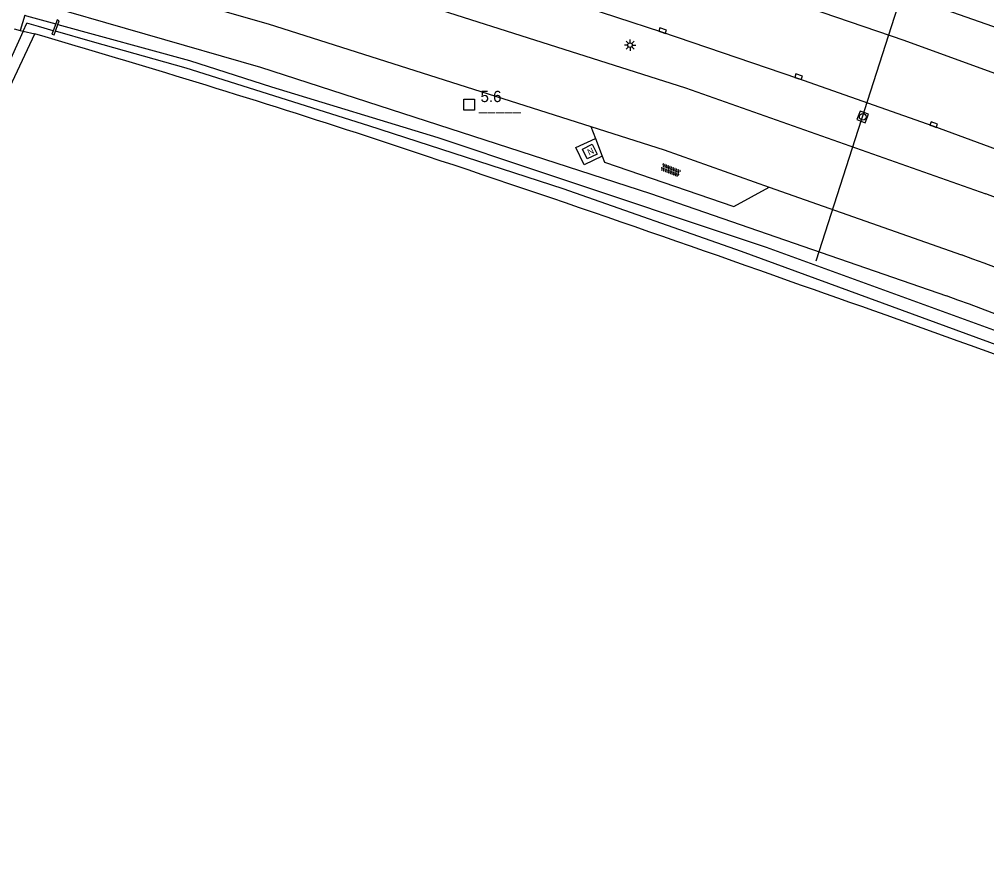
# Model space of a CAD drawing. Extents: x 133000 to 136000, y 400500 to 403500.
# Drawn here: x 134471.1 to 134578.4, y 401013 to 401106.1 of the extents above; entities that cross this region are included whole.
import ezdxf

# ---------------------------------------------------------------- set-up
doc = ezdxf.new("R2010")
doc.units = 0
for name, color, linetype in [('gg-knt-verharding', 7, 'Continuous'), ('gg-kntw-bovenkant insteek waterloop', 7, 'Continuous'), ('gg-kntw-waterlijn', 7, 'Continuous'), ('gg-kwrk-duiker nz buis', 7, 'Continuous'), ('gg-kwrk-kunstwerk', 7, 'Continuous'), ('gt-anno-nummer hm paal', 7, 'Continuous'), ('gt-grn-vlakafsluiter', 7, 'Continuous'), ('gt-symb-hm paal', 7, 'Continuous'), ('gt-symb-kolk', 7, 'Continuous'), ('gt-symb-lichtmast', 7, 'Continuous'), ('gt-symb-nortonput', 7, 'Continuous'), ('gt-symb-overige verharding', 7, 'Continuous'), ('gt-symb-rioolschacht', 7, 'Continuous')]:
    doc.layers.add(name, color=color, linetype=linetype)

# ---------------------------------------------------------------- blocks, each defined once
blk = doc.blocks.new('gt0-OVH')
at = {"layer": 'gt-symb-overige verharding'}
for points in [[(-0.97, 0.3), (-0.97, 0.31), (-0.96, 0.32), (-0.97, 0.33), (-0.97, 0.34), (-0.98, 0.35), (-0.99, 0.35), (-1, 0.36), (-1.01, 0.35), (-1.02, 0.35), (-1.03, 0.34), (-1.03, 0.33), (-1.04, 0.32), (-1.03, 0.31), (-1.03, 0.3), (-1.02, 0.29), (-1.01, 0.29), (-1, 0.28), (-0.99, 0.29), (-0.98, 0.29)], [(-0.87, 0.11), (-0.87, 0.12), (-0.86, 0.13), (-0.87, 0.14), (-0.87, 0.15), (-0.88, 0.16), (-0.89, 0.16), (-0.9, 0.16), (-0.91, 0.16), (-0.92, 0.16), (-0.93, 0.15), (-0.93, 0.14), (-0.94, 0.13), (-0.93, 0.12), (-0.93, 0.11), (-0.92, 0.1), (-0.91, 0.09), (-0.9, 0.09), (-0.89, 0.09), (-0.88, 0.1)], [(-0.77, 0.3), (-0.77, 0.31), (-0.76, 0.32), (-0.77, 0.33), (-0.77, 0.34), (-0.78, 0.35), (-0.79, 0.35), (-0.8, 0.36), (-0.81, 0.35), (-0.82, 0.35), (-0.83, 0.34), (-0.83, 0.33), (-0.84, 0.32), (-0.83, 0.31), (-0.83, 0.3), (-0.82, 0.29), (-0.81, 0.29), (-0.8, 0.28), (-0.79, 0.29), (-0.78, 0.29)], [(-0.67, 0.11), (-0.67, 0.12), (-0.66, 0.13), (-0.67, 0.14), (-0.67, 0.15), (-0.68, 0.16), (-0.69, 0.16), (-0.7, 0.16), (-0.71, 0.16), (-0.72, 0.16), (-0.73, 0.15), (-0.73, 0.14), (-0.74, 0.13), (-0.73, 0.12), (-0.73, 0.11), (-0.72, 0.1), (-0.71, 0.09), (-0.7, 0.09), (-0.69, 0.09), (-0.68, 0.1)], [(-0.57, 0.3), (-0.57, 0.31), (-0.56, 0.32), (-0.57, 0.33), (-0.57, 0.34), (-0.58, 0.35), (-0.59, 0.35), (-0.6, 0.36), (-0.61, 0.35), (-0.62, 0.35), (-0.63, 0.34), (-0.63, 0.33), (-0.64, 0.32), (-0.63, 0.31), (-0.63, 0.3), (-0.62, 0.29), (-0.61, 0.29), (-0.6, 0.28), (-0.59, 0.29), (-0.58, 0.29)], [(-0.47, 0.11), (-0.47, 0.12), (-0.46, 0.13), (-0.47, 0.14), (-0.47, 0.15), (-0.48, 0.16), (-0.49, 0.16), (-0.5, 0.16), (-0.51, 0.16), (-0.52, 0.16), (-0.53, 0.15), (-0.53, 0.14), (-0.54, 0.13), (-0.53, 0.12), (-0.53, 0.11), (-0.52, 0.1), (-0.51, 0.09), (-0.5, 0.09), (-0.49, 0.09), (-0.48, 0.1)], [(-0.37, 0.3), (-0.37, 0.31), (-0.36, 0.32), (-0.37, 0.33), (-0.37, 0.34), (-0.38, 0.35), (-0.39, 0.35), (-0.4, 0.36), (-0.41, 0.35), (-0.42, 0.35), (-0.43, 0.34), (-0.43, 0.33), (-0.44, 0.32), (-0.43, 0.31), (-0.43, 0.3), (-0.42, 0.29), (-0.41, 0.29), (-0.4, 0.28), (-0.39, 0.29), (-0.38, 0.29)], [(-0.27, 0.11), (-0.27, 0.12), (-0.26, 0.13), (-0.27, 0.14), (-0.27, 0.15), (-0.28, 0.16), (-0.29, 0.16), (-0.3, 0.16), (-0.31, 0.16), (-0.32, 0.16), (-0.33, 0.15), (-0.33, 0.14), (-0.34, 0.13), (-0.33, 0.12), (-0.33, 0.11), (-0.32, 0.1), (-0.31, 0.09), (-0.3, 0.09), (-0.29, 0.09), (-0.28, 0.1)], [(-0.17, 0.3), (-0.17, 0.31), (-0.16, 0.32), (-0.17, 0.33), (-0.17, 0.34), (-0.18, 0.35), (-0.19, 0.35), (-0.2, 0.36), (-0.21, 0.35), (-0.22, 0.35), (-0.23, 0.34), (-0.23, 0.33), (-0.24, 0.32), (-0.23, 0.31), (-0.23, 0.3), (-0.22, 0.29), (-0.21, 0.29), (-0.2, 0.28), (-0.19, 0.29), (-0.18, 0.29)], [(-0.07, 0.11), (-0.07, 0.12), (-0.06, 0.13), (-0.07, 0.14), (-0.07, 0.15), (-0.08, 0.16), (-0.09, 0.16), (-0.1, 0.16), (-0.11, 0.16), (-0.12, 0.16), (-0.13, 0.15), (-0.13, 0.14), (-0.14, 0.13), (-0.13, 0.12), (-0.13, 0.11), (-0.12, 0.1), (-0.11, 0.09), (-0.1, 0.09), (-0.09, 0.09), (-0.08, 0.1)], [(0.03, 0.3), (0.03, 0.31), (0.04, 0.32), (0.03, 0.33), (0.03, 0.34), (0.02, 0.35), (0.01, 0.35), (0, 0.36), (-0.01, 0.35), (-0.02, 0.35), (-0.03, 0.34), (-0.03, 0.33), (-0.04, 0.32), (-0.03, 0.31), (-0.03, 0.3), (-0.02, 0.29), (-0.01, 0.29), (0, 0.28), (0.01, 0.29), (0.02, 0.29)], [(0.13, 0.11), (0.13, 0.12), (0.14, 0.13), (0.13, 0.14), (0.13, 0.15), (0.12, 0.16), (0.11, 0.16), (0.1, 0.16), (0.09, 0.16), (0.08, 0.16), (0.07, 0.15), (0.07, 0.14), (0.06, 0.13), (0.07, 0.12), (0.07, 0.11), (0.08, 0.1), (0.09, 0.09), (0.1, 0.09), (0.11, 0.09), (0.12, 0.1)], [(0.23, 0.3), (0.23, 0.31), (0.24, 0.32), (0.23, 0.33), (0.23, 0.34), (0.22, 0.35), (0.21, 0.35), (0.2, 0.36), (0.19, 0.35), (0.18, 0.35), (0.17, 0.34), (0.17, 0.33), (0.16, 0.32), (0.17, 0.31), (0.17, 0.3), (0.18, 0.29), (0.19, 0.29), (0.2, 0.28), (0.21, 0.29), (0.22, 0.29)], [(0.33, 0.11), (0.33, 0.12), (0.34, 0.13), (0.33, 0.14), (0.33, 0.15), (0.32, 0.16), (0.31, 0.16), (0.3, 0.16), (0.29, 0.16), (0.28, 0.16), (0.27, 0.15), (0.27, 0.14), (0.26, 0.13), (0.27, 0.12), (0.27, 0.11), (0.28, 0.1), (0.29, 0.09), (0.3, 0.09), (0.31, 0.09), (0.32, 0.1)], [(0.43, 0.3), (0.43, 0.31), (0.44, 0.32), (0.43, 0.33), (0.43, 0.34), (0.42, 0.35), (0.41, 0.35), (0.4, 0.36), (0.39, 0.35), (0.38, 0.35), (0.37, 0.34), (0.37, 0.33), (0.36, 0.32), (0.37, 0.31), (0.37, 0.3), (0.38, 0.29), (0.39, 0.29), (0.4, 0.28), (0.41, 0.29), (0.42, 0.29)], [(0.53, 0.11), (0.53, 0.12), (0.54, 0.13), (0.53, 0.14), (0.53, 0.15), (0.52, 0.16), (0.51, 0.16), (0.5, 0.16), (0.49, 0.16), (0.48, 0.16), (0.47, 0.15), (0.47, 0.14), (0.46, 0.13), (0.47, 0.12), (0.47, 0.11), (0.48, 0.1), (0.49, 0.09), (0.5, 0.09), (0.51, 0.09), (0.52, 0.1)], [(0.63, 0.3), (0.63, 0.31), (0.64, 0.32), (0.63, 0.33), (0.63, 0.34), (0.62, 0.35), (0.61, 0.35), (0.6, 0.36), (0.59, 0.35), (0.58, 0.35), (0.57, 0.34), (0.57, 0.33), (0.56, 0.32), (0.57, 0.31), (0.57, 0.3), (0.58, 0.29), (0.59, 0.29), (0.6, 0.28), (0.61, 0.29), (0.62, 0.29)], [(0.73, 0.11), (0.73, 0.12), (0.74, 0.13), (0.73, 0.14), (0.73, 0.15), (0.72, 0.16), (0.71, 0.16), (0.7, 0.16), (0.69, 0.16), (0.68, 0.16), (0.67, 0.15), (0.67, 0.14), (0.66, 0.13), (0.67, 0.12), (0.67, 0.11), (0.68, 0.1), (0.69, 0.09), (0.7, 0.09), (0.71, 0.09), (0.72, 0.1)], [(0.83, 0.3), (0.83, 0.31), (0.84, 0.32), (0.83, 0.33), (0.83, 0.34), (0.82, 0.35), (0.81, 0.35), (0.8, 0.36), (0.79, 0.35), (0.78, 0.35), (0.77, 0.34), (0.77, 0.33), (0.76, 0.32), (0.77, 0.31), (0.77, 0.3), (0.78, 0.29), (0.79, 0.29), (0.8, 0.28), (0.81, 0.29), (0.82, 0.29)], [(0.93, 0.11), (0.93, 0.12), (0.94, 0.13), (0.93, 0.14), (0.93, 0.15), (0.92, 0.16), (0.91, 0.16), (0.9, 0.16), (0.89, 0.16), (0.88, 0.16), (0.87, 0.15), (0.87, 0.14), (0.86, 0.13), (0.87, 0.12), (0.87, 0.11), (0.88, 0.1), (0.89, 0.09), (0.9, 0.09), (0.91, 0.09), (0.92, 0.1)], [(1.03, 0.3), (1.03, 0.31), (1.04, 0.32), (1.03, 0.33), (1.03, 0.34), (1.02, 0.35), (1.01, 0.35), (1, 0.36), (0.99, 0.35), (0.98, 0.35), (0.97, 0.34), (0.97, 0.33), (0.96, 0.32), (0.97, 0.31), (0.97, 0.3), (0.98, 0.29), (0.99, 0.29), (1, 0.28), (1.01, 0.29), (1.02, 0.29)], [(-0.97, -0.14), (-0.97, -0.13), (-0.96, -0.12), (-0.97, -0.11), (-0.97, -0.1), (-0.98, -0.09), (-0.99, -0.09), (-1, -0.08), (-1.01, -0.09), (-1.02, -0.09), (-1.03, -0.1), (-1.03, -0.11), (-1.04, -0.12), (-1.03, -0.13), (-1.03, -0.14), (-1.02, -0.15), (-1.01, -0.15), (-1, -0.16), (-0.99, -0.15), (-0.98, -0.15)], [(-0.87, -0.33), (-0.87, -0.32), (-0.86, -0.31), (-0.87, -0.3), (-0.87, -0.29), (-0.88, -0.28), (-0.89, -0.28), (-0.9, -0.28), (-0.91, -0.28), (-0.92, -0.28), (-0.93, -0.29), (-0.93, -0.3), (-0.94, -0.31), (-0.93, -0.32), (-0.93, -0.33), (-0.92, -0.34), (-0.91, -0.35), (-0.9, -0.35), (-0.89, -0.35), (-0.88, -0.34)], [(-0.77, -0.14), (-0.77, -0.13), (-0.76, -0.12), (-0.77, -0.11), (-0.77, -0.1), (-0.78, -0.09), (-0.79, -0.09), (-0.8, -0.08), (-0.81, -0.09), (-0.82, -0.09), (-0.83, -0.1), (-0.83, -0.11), (-0.84, -0.12), (-0.83, -0.13), (-0.83, -0.14), (-0.82, -0.15), (-0.81, -0.15), (-0.8, -0.16), (-0.79, -0.15), (-0.78, -0.15)], [(-0.67, -0.33), (-0.67, -0.32), (-0.66, -0.31), (-0.67, -0.3), (-0.67, -0.29), (-0.68, -0.28), (-0.69, -0.28), (-0.7, -0.28), (-0.71, -0.28), (-0.72, -0.28), (-0.73, -0.29), (-0.73, -0.3), (-0.74, -0.31), (-0.73, -0.32), (-0.73, -0.33), (-0.72, -0.34), (-0.71, -0.35), (-0.7, -0.35), (-0.69, -0.35), (-0.68, -0.34)], [(-0.57, -0.14), (-0.57, -0.13), (-0.56, -0.12), (-0.57, -0.11), (-0.57, -0.1), (-0.58, -0.09), (-0.59, -0.09), (-0.6, -0.08), (-0.61, -0.09), (-0.62, -0.09), (-0.63, -0.1), (-0.63, -0.11), (-0.64, -0.12), (-0.63, -0.13), (-0.63, -0.14), (-0.62, -0.15), (-0.61, -0.15), (-0.6, -0.16), (-0.59, -0.15), (-0.58, -0.15)], [(-0.47, -0.33), (-0.47, -0.32), (-0.46, -0.31), (-0.47, -0.3), (-0.47, -0.29), (-0.48, -0.28), (-0.49, -0.28), (-0.5, -0.28), (-0.51, -0.28), (-0.52, -0.28), (-0.53, -0.29), (-0.53, -0.3), (-0.54, -0.31), (-0.53, -0.32), (-0.53, -0.33), (-0.52, -0.34), (-0.51, -0.35), (-0.5, -0.35), (-0.49, -0.35), (-0.48, -0.34)], [(-0.37, -0.14), (-0.37, -0.13), (-0.36, -0.12), (-0.37, -0.11), (-0.37, -0.1), (-0.38, -0.09), (-0.39, -0.09), (-0.4, -0.08), (-0.41, -0.09), (-0.42, -0.09), (-0.43, -0.1), (-0.43, -0.11), (-0.44, -0.12), (-0.43, -0.13), (-0.43, -0.14), (-0.42, -0.15), (-0.41, -0.15), (-0.4, -0.16), (-0.39, -0.15), (-0.38, -0.15)], [(-0.27, -0.33), (-0.27, -0.32), (-0.26, -0.31), (-0.27, -0.3), (-0.27, -0.29), (-0.28, -0.28), (-0.29, -0.28), (-0.3, -0.28), (-0.31, -0.28), (-0.32, -0.28), (-0.33, -0.29), (-0.33, -0.3), (-0.34, -0.31), (-0.33, -0.32), (-0.33, -0.33), (-0.32, -0.34), (-0.31, -0.35), (-0.3, -0.35), (-0.29, -0.35), (-0.28, -0.34)], [(-0.17, -0.14), (-0.17, -0.13), (-0.16, -0.12), (-0.17, -0.11), (-0.17, -0.1), (-0.18, -0.09), (-0.19, -0.09), (-0.2, -0.08), (-0.21, -0.09), (-0.22, -0.09), (-0.23, -0.1), (-0.23, -0.11), (-0.24, -0.12), (-0.23, -0.13), (-0.23, -0.14), (-0.22, -0.15), (-0.21, -0.15), (-0.2, -0.16), (-0.19, -0.15), (-0.18, -0.15)], [(-0.07, -0.33), (-0.07, -0.32), (-0.06, -0.31), (-0.07, -0.3), (-0.07, -0.29), (-0.08, -0.28), (-0.09, -0.28), (-0.1, -0.28), (-0.11, -0.28), (-0.12, -0.28), (-0.13, -0.29), (-0.13, -0.3), (-0.14, -0.31), (-0.13, -0.32), (-0.13, -0.33), (-0.12, -0.34), (-0.11, -0.35), (-0.1, -0.35), (-0.09, -0.35), (-0.08, -0.34)], [(0.03, -0.14), (0.03, -0.13), (0.04, -0.12), (0.03, -0.11), (0.03, -0.1), (0.02, -0.09), (0.01, -0.09), (0, -0.08), (-0.01, -0.09), (-0.02, -0.09), (-0.03, -0.1), (-0.03, -0.11), (-0.04, -0.12), (-0.03, -0.13), (-0.03, -0.14), (-0.02, -0.15), (-0.01, -0.15), (0, -0.16), (0.01, -0.15), (0.02, -0.15)], [(0.13, -0.33), (0.13, -0.32), (0.14, -0.31), (0.13, -0.3), (0.13, -0.29), (0.12, -0.28), (0.11, -0.28), (0.1, -0.28), (0.09, -0.28), (0.08, -0.28), (0.07, -0.29), (0.07, -0.3), (0.06, -0.31), (0.07, -0.32), (0.07, -0.33), (0.08, -0.34), (0.09, -0.35), (0.1, -0.35), (0.11, -0.35), (0.12, -0.34)], [(0.23, -0.14), (0.23, -0.13), (0.24, -0.12), (0.23, -0.11), (0.23, -0.1), (0.22, -0.09), (0.21, -0.09), (0.2, -0.08), (0.19, -0.09), (0.18, -0.09), (0.17, -0.1), (0.17, -0.11), (0.16, -0.12), (0.17, -0.13), (0.17, -0.14), (0.18, -0.15), (0.19, -0.15), (0.2, -0.16), (0.21, -0.15), (0.22, -0.15)], [(0.33, -0.33), (0.33, -0.32), (0.34, -0.31), (0.33, -0.3), (0.33, -0.29), (0.32, -0.28), (0.31, -0.28), (0.3, -0.28), (0.29, -0.28), (0.28, -0.28), (0.27, -0.29), (0.27, -0.3), (0.26, -0.31), (0.27, -0.32), (0.27, -0.33), (0.28, -0.34), (0.29, -0.35), (0.3, -0.35), (0.31, -0.35), (0.32, -0.34)], [(0.43, -0.14), (0.43, -0.13), (0.44, -0.12), (0.43, -0.11), (0.43, -0.1), (0.42, -0.09), (0.41, -0.09), (0.4, -0.08), (0.39, -0.09), (0.38, -0.09), (0.37, -0.1), (0.37, -0.11), (0.36, -0.12), (0.37, -0.13), (0.37, -0.14), (0.38, -0.15), (0.39, -0.15), (0.4, -0.16), (0.41, -0.15), (0.42, -0.15)], [(0.53, -0.33), (0.53, -0.32), (0.54, -0.31), (0.53, -0.3), (0.53, -0.29), (0.52, -0.28), (0.51, -0.28), (0.5, -0.28), (0.49, -0.28), (0.48, -0.28), (0.47, -0.29), (0.47, -0.3), (0.46, -0.31), (0.47, -0.32), (0.47, -0.33), (0.48, -0.34), (0.49, -0.35), (0.5, -0.35), (0.51, -0.35), (0.52, -0.34)], [(0.63, -0.14), (0.63, -0.13), (0.64, -0.12), (0.63, -0.11), (0.63, -0.1), (0.62, -0.09), (0.61, -0.09), (0.6, -0.08), (0.59, -0.09), (0.58, -0.09), (0.57, -0.1), (0.57, -0.11), (0.56, -0.12), (0.57, -0.13), (0.57, -0.14), (0.58, -0.15), (0.59, -0.15), (0.6, -0.16), (0.61, -0.15), (0.62, -0.15)], [(0.73, -0.33), (0.73, -0.32), (0.74, -0.31), (0.73, -0.3), (0.73, -0.29), (0.72, -0.28), (0.71, -0.28), (0.7, -0.28), (0.69, -0.28), (0.68, -0.28), (0.67, -0.29), (0.67, -0.3), (0.66, -0.31), (0.67, -0.32), (0.67, -0.33), (0.68, -0.34), (0.69, -0.35), (0.7, -0.35), (0.71, -0.35), (0.72, -0.34)], [(0.83, -0.14), (0.83, -0.13), (0.84, -0.12), (0.83, -0.11), (0.83, -0.1), (0.82, -0.09), (0.81, -0.09), (0.8, -0.08), (0.79, -0.09), (0.78, -0.09), (0.77, -0.1), (0.77, -0.11), (0.76, -0.12), (0.77, -0.13), (0.77, -0.14), (0.78, -0.15), (0.79, -0.15), (0.8, -0.16), (0.81, -0.15), (0.82, -0.15)], [(0.93, -0.33), (0.93, -0.32), (0.94, -0.31), (0.93, -0.3), (0.93, -0.29), (0.92, -0.28), (0.91, -0.28), (0.9, -0.28), (0.89, -0.28), (0.88, -0.28), (0.87, -0.29), (0.87, -0.3), (0.86, -0.31), (0.87, -0.32), (0.87, -0.33), (0.88, -0.34), (0.89, -0.35), (0.9, -0.35), (0.91, -0.35), (0.92, -0.34)], [(1.03, -0.14), (1.03, -0.13), (1.04, -0.12), (1.03, -0.11), (1.03, -0.1), (1.02, -0.09), (1.01, -0.09), (1, -0.08), (0.99, -0.09), (0.98, -0.09), (0.97, -0.1), (0.97, -0.11), (0.96, -0.12), (0.97, -0.13), (0.97, -0.14), (0.98, -0.15), (0.99, -0.15), (1, -0.16), (1.01, -0.15), (1.02, -0.15)]]:
    blk.add_lwpolyline(points, close=True, dxfattribs=at)
blk = doc.blocks.new('gt0-NPUT')
at = {"layer": 'gt-symb-nortonput'}
blk.add_lwpolyline([(-0.57, -0.61), (-0.57, 0.59), (0.63, 0.59), (0.63, -0.61)], close=True, dxfattribs=at)
blk.add_text('N', height=0.7, dxfattribs=at).set_placement((-0.22, -0.38))
blk = doc.blocks.new('gt0-KOLK')
at = {"layer": 'gt-symb-kolk'}
blk.add_lwpolyline([(0, 0), (0.38, 0), (0.38, 0.4), (-0.37, 0.4), (-0.37, 0), (0, 0)], dxfattribs=at)
blk = doc.blocks.new('gt0-RS')
at = {"layer": 'gt-symb-rioolschacht'}
blk.add_lwpolyline([(-0.5, -0.5), (0.5, -0.5), (0.5, 0.5), (-0.5, 0.5)], close=True, dxfattribs=at)
blk.add_circle((0, 0), 0.375, dxfattribs=at)
blk = doc.blocks.new('gt0-HMpaal')
at = {"layer": 'gt-symb-hm paal'}
blk.add_lwpolyline([(-0.6, 0.6), (0.6, 0.6), (0.6, -0.6), (-0.6, -0.6)], close=True, dxfattribs=at)
blk = doc.blocks.new('gt0-LMAST')
at = {"layer": 'gt-symb-lichtmast'}
for p, q in [((-0.18, 0.17), (-0.45, 0.44)), ((-0.01, 0.25), (-0.01, 0.62)), ((0.17, 0.17), (0.44, 0.44)), ((-0.26, 0), (-0.63, 0)), ((-0.18, -0.18), (-0.45, -0.45)), ((-0.01, -0.25), (-0.01, -0.63)), ((0.44, -0.45), (0.17, -0.18)), ((0.24, 0), (0.62, 0))]:
    blk.add_line(p, q, dxfattribs=at)
blk.add_circle((-0.01, 0), 0.25, dxfattribs=at)

msp = doc.modelspace()

# ---------------------------------------------------------------- linework, layer by layer
at = {"layer": 'gg-knt-verharding'}
for p, q in [((134534.47, 401094.23), (134534.98, 401092.91)), ((134534.98, 401092.91), (134535.74, 401090.93)), ((134554.26, 401087.52), (134575.58, 401080))]:
    msp.add_line(p, q, dxfattribs=at)
for points in [[(134759.94, 401019.66), (134750.06, 401024.92), (134731.02, 401034.62), (134708.84, 401045.61), (134686.48, 401056.07), (134667.18, 401064.84), (134646.15, 401073.93), (134626.48, 401082.05), (134605.44, 401090.35), (134591.87, 401095.51), (134569.22, 401103.78), (134545.1, 401112.07), (134521.01, 401119.87), (134495.9, 401127.48), (134470.17, 401134.86), (134469.21, 401135.11)], [(134755.74, 401013.02), (134753.25, 401014.35), (134738.05, 401022.3), (134723.08, 401029.88), (134707.89, 401037.33), (134692.66, 401044.61), (134677.66, 401051.53), (134662.61, 401058.26), (134647.51, 401064.78), (134641.23, 401067.44), (134632.49, 401071.1), (134617.48, 401077.19), (134602.47, 401083.1), (134588.45, 401088.36), (134587.47, 401088.74), (134572.43, 401094.26), (134557.44, 401099.56), (134542.37, 401104.68), (134527.4, 401109.6), (134512.34, 401114.35), (134497.32, 401118.87), (134482.27, 401123.27), (134467.37, 401127.46), (134466.25, 401127.76)], [(134464.32, 401122.98), (134501.27, 401112.45), (134544.96, 401098.51), (134578.27, 401086.75)], [(134461.61, 401116.24), (134498.7, 401105.62), (134534.47, 401094.23)], [(134534.47, 401094.23), (134542.61, 401091.63), (134554.26, 401087.52)], [(134535.74, 401090.93), (134533.73, 401089.99), (134532.82, 401091.9), (134534.98, 401092.91)], [(134535.74, 401090.93), (134535.99, 401090.28), (134550.33, 401085.35), (134554.26, 401087.52)]]:
    msp.add_lwpolyline(points, dxfattribs=at)
for centre, radius, start, end in [((134022.22, 399590.36), 1596.36, 68.04888, 69.61517), ((133988.53, 399497.04), 1688.31, 68.18799, 69.65253)]:
    msp.add_arc(centre, radius, start, end, dxfattribs=at)
at = {"layer": 'gg-kntw-bovenkant insteek waterloop'}
msp.add_line((134461.86, 401081.3), (134472.84, 401104.5), dxfattribs=at)
for points in [[(134592.99, 401100.44), (134572.42, 401107.64), (134550.61, 401115.22), (134530.23, 401122.02), (134508.65, 401128.64), (134490.26, 401134.3), (134487.65, 401135.02)], [(134472.2, 401108.21), (134497.86, 401100.82), (134541.09, 401086.81), (134573.93, 401075.45)]]:
    msp.add_lwpolyline(points, dxfattribs=at)
for centre, radius, start, end in [((134143.17, 399970.42), 1181.02, 71.98049, 73.79103), ((133895.94, 399226.2), 1965.22, 70.31772, 71.83816), ((134073.18, 399686.14), 1472.51, 69.01536, 70.78384), ((134046.21, 399667.12), 1503.96, 67.81822, 69.45832)]:
    msp.add_arc(centre, radius, start, end, dxfattribs=at)
at = {"layer": 'gg-kntw-waterlijn'}
msp.add_line((134471.54, 401104.81), (134471.94, 401105.69), dxfattribs=at)
for points in [[(134471.71, 401106.57), (134471.89, 401106.52), (134475.14, 401105.62)], [(134474.87, 401104.86), (134473.23, 401105.32), (134471.94, 401105.69)], [(134475.39, 401105.55), (134489.99, 401101.54), (134499.06, 401098.63), (134517.5, 401093.02), (134528.35, 401089.39), (134553.93, 401080.85), (134580.74, 401071.1)], [(134471.54, 401104.81), (134469.08, 401099.42), (134455.18, 401069.97), (134447.04, 401054.4), (134436.66, 401034.22), (134429.15, 401019.87)], [(134592.83, 401065.1), (134551.19, 401080.38), (134531.4, 401087.33), (134509.85, 401094.3), (134489.62, 401100.7), (134479.24, 401103.62), (134475.12, 401104.79)]]:
    msp.add_lwpolyline(points, dxfattribs=at)
at = {"layer": 'gg-kwrk-duiker nz buis'}
msp.add_line((134559.47, 401079.32), (134568.94, 401108.85), dxfattribs=at)
at = {"layer": 'gg-kwrk-kunstwerk'}
for p, q in [((134475.14, 401105.62), (134474.87, 401104.86)), ((134475.12, 401104.79), (134475.39, 401105.55)), ((134474.99, 401104.4), (134475.12, 401104.79))]:
    msp.add_line(p, q, dxfattribs=at)
for points in [[(134475.39, 401105.55), (134475.53, 401105.96), (134475.3, 401106.05), (134475.14, 401105.62)], [(134474.87, 401104.86), (134474.73, 401104.49), (134474.99, 401104.4)]]:
    msp.add_lwpolyline(points, dxfattribs=at)
at = {"layer": 'gt-grn-vlakafsluiter'}
for p, q in [((134471.71, 401106.57), (134471.2, 401104.89)), ((134470.53, 401105.05), (134471.2, 401104.89)), ((134471.2, 401104.89), (134471.54, 401104.81)), ((134471.54, 401104.81), (134472.84, 401104.5))]:
    msp.add_line(p, q, dxfattribs=at)

# ---------------------------------------------------------------- block references
at = {"layer": 'gt-symb-hm paal'}
msp.add_blockref('gt0-HMpaal', (134520.99, 401096.65), dxfattribs=at)
at = {"layer": 'gt-symb-kolk'}
for p, rotation in [((134542.37, 401104.68), -18.779117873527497), ((134557.44, 401099.56), -19.503573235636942), ((134572.43, 401094.26), -20.120165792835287)]:
    msp.add_blockref('gt0-KOLK', p, dxfattribs=dict(at, rotation=rotation))
at = {"layer": 'gt-symb-lichtmast'}
msp.add_blockref('gt0-LMAST', (134538.84, 401103.26), dxfattribs=at)
at = {"layer": 'gt-symb-nortonput', "rotation": 26.15525374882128}
msp.add_blockref('gt0-NPUT', (134534.33, 401091.45), dxfattribs=at)
at = {"layer": 'gt-symb-overige verharding', "rotation": -21.407739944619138}
msp.add_blockref('gt0-OVH', (134543.32, 401089.38), dxfattribs=at)
at = {"layer": 'gt-symb-rioolschacht', "rotation": -21.407739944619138}
msp.add_blockref('gt0-RS', (134564.63, 401095.3), dxfattribs=at)

# ---------------------------------------------------------------- texts
at = {"layer": 'gt-anno-nummer hm paal'}
msp.add_text('5.6', height=1.25, dxfattribs=at).set_placement((134522.25, 401096.94))
at = {"layer": 'gt-symb-hm paal'}
msp.add_text('_____', height=1.25, dxfattribs=at).set_placement((134522.07, 401096.04))

doc.saveas('drawing.dxf')
